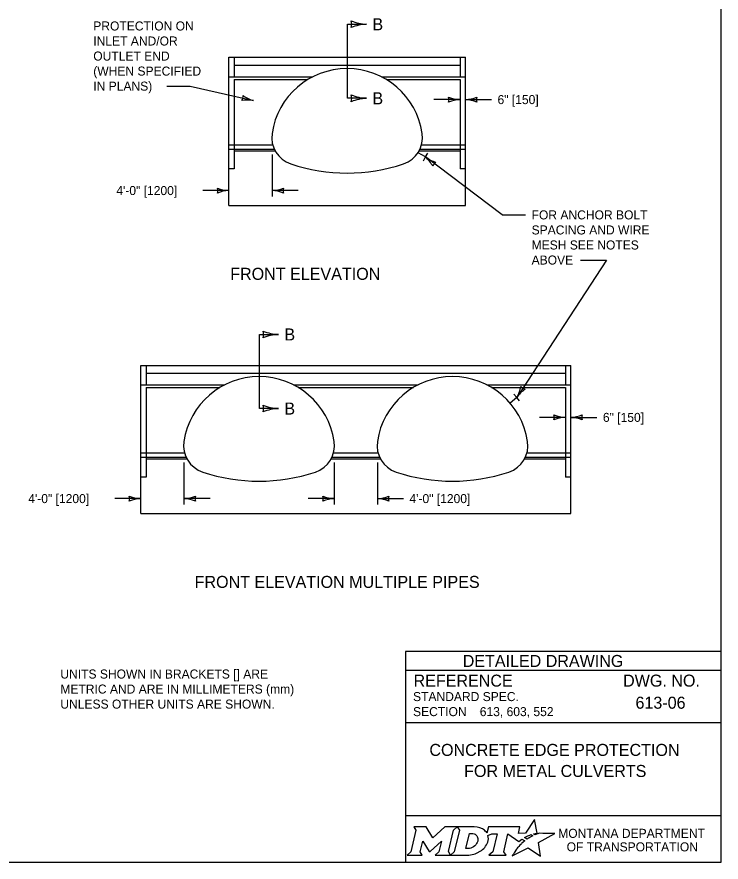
# Model space of a CAD drawing. Extents: x 49991.4 to 50021, y 49987.6 to 50011.4.
# Drawn here: x 50003.93 to 50008.61, y 50000.06 to 50005.68 of the extents above; entities that cross this region are included whole.
import ezdxf

# ---------------------------------------------------------------- set-up
doc = ezdxf.new("R2010")
doc.units = 0
for name, color, linetype in [('Level 1', 7, 'Continuous'), ('Level 2', 7, 'Continuous'), ('Level 3', 7, 'Continuous'), ('Level 4', 7, 'Continuous'), ('Level 6', 7, 'Continuous')]:
    doc.layers.add(name, color=color, linetype=linetype)

msp = doc.modelspace()

# ---------------------------------------------------------------- linework, layer by layer
at = {"layer": 'Level 1'}
for p, q in [((50005.3392, 50004.4278), (50005.3392, 50005.4139)), ((50005.3392, 50005.4139), (50006.9137, 50005.4139)), ((50006.9137, 50004.4278), (50006.9137, 50005.4139)), ((50005.3392, 50004.8321), (50005.6311, 50004.8321)), ((50006.6219, 50004.8324), (50006.9137, 50004.8324)), ((50005.3392, 50004.8032), (50005.6415, 50004.8032)), ((50006.6481, 50004.751), (50006.5984, 50004.7796)), ((50006.6113, 50004.8032), (50006.9137, 50004.8032)), ((50006.6481, 50004.751), (50006.6625, 50004.7759)), ((50006.6336, 50004.726), (50006.6481, 50004.751)), ((50005.3392, 50004.4278), (50006.9137, 50004.4278)), ((50004.7532, 50002.3794), (50004.7532, 50003.3655)), ((50004.7532, 50003.3655), (50007.6147, 50003.3655)), ((50007.6147, 50002.3794), (50007.6147, 50003.3655)), ((50007.2545, 50003.1521), (50007.2101, 50003.1149)), ((50007.2545, 50003.1521), (50007.2359, 50003.1738)), ((50007.2729, 50003.1299), (50007.2545, 50003.1521)), ((50004.7532, 50002.7837), (50005.0451, 50002.7837)), ((50004.7533, 50002.7548), (50005.0556, 50002.7548)), ((50006.0253, 50002.7548), (50006.3426, 50002.7548)), ((50006.0358, 50002.7837), (50006.3321, 50002.7837)), ((50007.3123, 50002.7548), (50007.6147, 50002.7548)), ((50007.3228, 50002.7837), (50007.6147, 50002.7837)), ((50004.7532, 50002.3794), (50007.6147, 50002.3794))]:
    msp.add_line(p, q, dxfattribs=at)
msp.add_lwpolyline([(50008.6146, 50011.2628), (50000.3356, 50011.2628), (50000.3356, 50000.0624), (50008.6146, 50000.0624)], close=True, dxfattribs=at)
for centre, radius, start, end in [((50006.1264, 50004.8333), 0.5053, 8.4935, 171.5065), ((50005.8103, 50004.8805), 0.1857, 171.5065, 251.5631), ((50006.4425, 50004.8805), 0.1857, 288.4369, 8.4935), ((50006.1264, 50005.8288), 1.1852, 251.5631, 288.4369), ((50005.5405, 50002.785), 0.5053, 8.4935, 171.5065), ((50006.8274, 50002.785), 0.5053, 8.4935, 171.5065), ((50005.2243, 50002.8322), 0.1857, 171.5065, 251.5631), ((50005.8566, 50002.8322), 0.1857, 288.4369, 8.4935), ((50006.5113, 50002.8322), 0.1857, 171.5065, 251.5631), ((50007.1436, 50002.8322), 0.1857, 288.4369, 8.4935), ((50005.5405, 50003.7805), 1.1852, 251.5631, 288.4369), ((50006.8274, 50003.7805), 1.1852, 251.5631, 288.4369)]:
    msp.add_arc(centre, radius, start, end, dxfattribs=at)
at = {"layer": 'Level 2'}
for p, q in [((50008.6146, 50001.4624), (50006.5146, 50001.4624)), ((50006.5146, 50001.4624), (50006.5146, 50000.0624)), ((50008.6146, 50001.3374), (50006.5146, 50001.3374)), ((50008.2507, 50001.1223), (50008.2507, 50001.1223)), ((50007.0089, 50001.0629), (50007.0089, 50001.0629)), ((50008.6146, 50000.9874), (50006.5146, 50000.9874)), ((50007.5646, 50000.7383), (50007.5646, 50000.7383)), ((50008.6146, 50000.3693), (50006.5146, 50000.3693))]:
    msp.add_line(p, q, dxfattribs=at)
for points in [[(50007.3771, 50000.2447), (50007.3668, 50000.2503), (50007.3784, 50000.2531), (50007.39, 50000.2551), (50007.3726, 50000.3452), (50007.3131, 50000.2539), (50007.2658, 50000.2532), (50007.2761, 50000.2973), (50007.0669, 50000.2974), (50007.0568, 50000.2549), (50007.051, 50000.2632)], [(50006.5701, 50000.2974), (50006.5842, 50000.274), (50006.5507, 50000.1307), (50006.525, 50000.1082), (50006.6266, 50000.1082), (50006.6131, 50000.131), (50006.6293, 50000.2011), (50006.673, 50000.1321), (50006.6783, 50000.1321), (50006.7534, 50000.2016), (50006.737, 50000.1305), (50006.7123, 50000.1085), (50006.8139, 50000.1085), (50006.8001, 50000.1318), (50006.8333, 50000.2742)], [(50006.8333, 50000.2742), (50006.8586, 50000.2974), (50006.7762, 50000.2974), (50006.6966, 50000.2244), (50006.6521, 50000.2971), (50006.5701, 50000.2974)], [(50006.9722, 50000.2974), (50006.8586, 50000.2974), (50006.8733, 50000.2745), (50006.8394, 50000.1307), (50006.8139, 50000.1085), (50006.9245, 50000.1085)], [(50006.9962, 50000.2107), (50006.995, 50000.2026), (50006.9918, 50000.1933), (50006.9876, 50000.1851), (50006.982, 50000.1776), (50006.9755, 50000.1707), (50006.9676, 50000.1644), (50006.9593, 50000.1597), (50006.9502, 50000.1558), (50006.9411, 50000.1535), (50006.9319, 50000.1526), (50006.916, 50000.1526), (50006.9396, 50000.2526), (50006.9556, 50000.2526), (50006.9632, 50000.252), (50006.9708, 50000.2501), (50006.9774, 50000.2471), (50006.9835, 50000.2429), (50006.9883, 50000.2379), (50006.992, 50000.2319), (50006.9947, 50000.2257), (50006.9963, 50000.2183), (50006.9963, 50000.2153), (50006.9962, 50000.2107)], [(50007.0636, 50000.2383), (50007.0882, 50000.2514), (50007.1251, 50000.2514), (50007.0965, 50000.1309), (50007.069, 50000.1082), (50007.1852, 50000.1082), (50007.1682, 50000.1311), (50007.1964, 50000.2513), (50007.2677, 50000.1996), (50007.2888, 50000.2147), (50007.3085, 50000.2038)], [(50007.2527, 50000.1479), (50007.2374, 50000.1235), (50007.2327, 50000.116), (50007.2269, 50000.1074), (50007.2246, 50000.1031), (50007.3299, 50000.1562), (50007.4138, 50000.1011), (50007.4007, 50000.1938), (50007.5076, 50000.2522), (50007.4583, 50000.253), (50007.4282, 50000.2534), (50007.4074, 50000.2537), (50007.4006, 50000.2522), (50007.3957, 50000.251), (50007.3873, 50000.2487), (50007.3771, 50000.2447)], [(50007.3267, 50000.2171), (50007.3243, 50000.2154), (50007.306, 50000.225), (50007.3163, 50000.2307), (50007.3204, 50000.2329), (50007.329, 50000.2369), (50007.3347, 50000.2395), (50007.3426, 50000.2425), (50007.3499, 50000.2452), (50007.3617, 50000.2378), (50007.3577, 50000.2357), (50007.3531, 50000.2332), (50007.3489, 50000.231), (50007.3439, 50000.2281), (50007.342, 50000.227), (50007.3393, 50000.2254), (50007.3368, 50000.224), (50007.3345, 50000.2224), (50007.3319, 50000.2206), (50007.3292, 50000.2188), (50007.3267, 50000.2171)], [(50007.2666, 50000.164), (50007.2666, 50000.164)], [(50006.9702, 50000.1158), (50006.9786, 50000.1184), (50006.9916, 50000.1238), (50007.012, 50000.1348)]]:
    msp.add_lwpolyline(points, dxfattribs=at)
for centre, radius, start, end in [((50006.9953, 50000.219), 0.0709, 339.5329, 15.8582), ((50006.9513, 50000.2363), 0.1183, 300.9103, 339.1383)]:
    msp.add_arc(centre, radius, start, end, dxfattribs=at)
for centre, major_axis, ratio, start_param, end_param in [((50006.9701, 50000.25), (0.0834, -0.0037), 0.568097, 0.61298, 1.570796), ((50007.0257, 50000.2573), (0.0361, -0.0295), 0.469099, 1.225588, 1.570796), ((50007.2597, 50000.1559), (-0.00694, -0.00806), 0.008222, 0, 3.137361), ((50007.2764, 50000.1742), (-0.0098, -0.0102), 0.016458, 3.141593, 6.279097), ((50007.2974, 50000.1941), (-0.0112, -0.0097), 0.021651, 3.157348, 6.283185), ((50006.9248, 50000.2568), (0, 0.1484), 0.987302, 3.139398, 3.456847)]:
    msp.add_ellipse(centre, major_axis=major_axis, ratio=ratio, start_param=start_param, end_param=end_param, dxfattribs=at)
at = {"layer": 'Level 3'}
for p, q in [((50004.9262, 50005.2221), (50005.0829, 50005.2221)), ((50005.0829, 50005.2221), (50005.5041, 50005.1256)), ((50006.8777, 50005.1324), (50006.7043, 50005.1324)), ((50006.9137, 50005.1326), (50007.0871, 50005.1326)), ((50005.6267, 50004.7679), (50005.6267, 50004.4878)), ((50007.1571, 50004.3658), (50006.6481, 50004.751)), ((50005.3392, 50004.5278), (50005.1658, 50004.5278)), ((50005.8001, 50004.5278), (50005.6267, 50004.5278)), ((50007.1571, 50004.3658), (50007.3138, 50004.3658)), ((50007.8511, 50004.0658), (50007.2545, 50003.1521)), ((50007.6786, 50004.0658), (50007.8511, 50004.0658)), ((50007.5787, 50003.0194), (50007.4053, 50003.0194)), ((50007.6147, 50003.0194), (50007.7881, 50003.0194)), ((50005.0407, 50002.7196), (50005.0407, 50002.4394)), ((50006.0402, 50002.7196), (50006.0402, 50002.4394)), ((50006.3277, 50002.7196), (50006.3277, 50002.4394)), ((50004.7532, 50002.4794), (50004.5798, 50002.4794)), ((50005.2141, 50002.4794), (50005.0407, 50002.4794)), ((50006.0402, 50002.4794), (50005.8668, 50002.4794)), ((50006.3277, 50002.4794), (50006.5011, 50002.4794))]:
    msp.add_line(p, q, dxfattribs=at)
for centre, radius, start, end in [((50006.2671, 50005.9297), 0.2964, 247.456, 267.6395), ((50006.0839, 50005.6335), 0.073, 342.1388, 17.8612), ((50006.2702, 50005.3232), 0.3107, 92.8273, 112.0772), ((50005.3791, 50005.1543), 0.0548, 329.2405, 4.9629), ((50005.5626, 50005.3401), 0.2223, 234.5577, 254.7412), ((50006.2671, 50005.4372), 0.2964, 247.456, 267.6395), ((50006.0839, 50005.141), 0.073, 342.1388, 17.8612), ((50005.4634, 50004.8962), 0.233, 79.929, 99.1789), ((50006.2702, 50004.8307), 0.3107, 92.8273, 112.0772), ((50006.8868, 50005.3545), 0.2223, 247.456, 267.6395), ((50006.7495, 50005.1324), 0.0548, 342.1388, 17.8612), ((50006.8892, 50004.8997), 0.233, 92.8273, 112.0772), ((50006.9022, 50005.3653), 0.233, 272.8273, 292.0772), ((50006.9045, 50004.9105), 0.2223, 67.456, 87.6395), ((50007.0419, 50005.1326), 0.0548, 162.1388, 197.8612), ((50006.4997, 50004.5853), 0.2223, 27.9694, 48.1529), ((50006.7872, 50004.9379), 0.233, 233.3407, 252.5906), ((50006.747, 50004.6694), 0.0548, 122.6522, 158.3746), ((50005.3483, 50004.7499), 0.2223, 247.456, 267.6395), ((50005.211, 50004.5278), 0.0548, 342.1388, 17.8612), ((50005.6152, 50004.7605), 0.233, 272.8273, 292.0772), ((50005.7549, 50004.5278), 0.0548, 162.1388, 197.8612), ((50005.3507, 50004.2951), 0.233, 92.8273, 112.0772), ((50005.6175, 50004.3057), 0.2223, 67.456, 87.6395), ((50005.6812, 50003.867), 0.2964, 247.456, 267.6395), ((50005.498, 50003.5708), 0.073, 342.1388, 17.8612), ((50005.6843, 50003.2605), 0.3107, 92.8273, 112.0772), ((50007.0534, 50003.2697), 0.233, 329.6853, 348.9351), ((50007.4355, 50003.023), 0.2223, 124.314, 144.4975), ((50007.3246, 50003.2595), 0.0548, 218.9968, 254.7191), ((50005.6812, 50003.3745), 0.2964, 247.456, 267.6395), ((50005.498, 50003.0783), 0.073, 342.1388, 17.8612), ((50005.6843, 50002.768), 0.3107, 92.8273, 112.0772), ((50007.5879, 50003.2415), 0.2223, 247.456, 267.6395), ((50007.4505, 50003.0194), 0.0548, 342.1388, 17.8612), ((50007.6032, 50003.2521), 0.233, 272.8273, 292.0772), ((50007.7429, 50003.0194), 0.0548, 162.1388, 197.8612), ((50007.5902, 50002.7867), 0.233, 92.8273, 112.0772), ((50007.6055, 50002.7973), 0.2223, 67.456, 87.6395), ((50004.7624, 50002.7015), 0.2223, 247.456, 267.6395), ((50004.625, 50002.4794), 0.0548, 342.1388, 17.8612), ((50004.7647, 50002.2467), 0.233, 92.8273, 112.0772), ((50005.0292, 50002.7121), 0.233, 272.8273, 292.0772), ((50005.0315, 50002.2573), 0.2223, 67.456, 87.6395), ((50005.1689, 50002.4794), 0.0548, 162.1388, 197.8612), ((50006.0494, 50002.7015), 0.2223, 247.456, 267.6395), ((50005.912, 50002.4794), 0.0548, 342.1388, 17.8612), ((50006.0517, 50002.2467), 0.233, 92.8273, 112.0772), ((50006.3162, 50002.7121), 0.233, 272.8273, 292.0772), ((50006.3185, 50002.2573), 0.2223, 67.456, 87.6395), ((50006.4559, 50002.4794), 0.0548, 162.1388, 197.8612)]:
    msp.add_arc(centre, radius, start, end, dxfattribs=at)
at = {"layer": 'Level 4'}
for p, q in [((50005.3751, 50005.4139), (50005.3751, 50005.284)), ((50006.8777, 50005.4139), (50006.8777, 50005.2846)), ((50005.3751, 50005.3625), (50006.8777, 50005.3625)), ((50005.3392, 50005.284), (50005.8985, 50005.284)), ((50006.3547, 50005.2846), (50006.9137, 50005.2846)), ((50005.3751, 50005.2667), (50005.3751, 50004.6714)), ((50005.3751, 50005.2667), (50005.8624, 50005.2667)), ((50006.3875, 50005.2668), (50006.8777, 50005.2668)), ((50006.8777, 50005.2668), (50006.8777, 50004.6712)), ((50005.3751, 50004.7916), (50005.6473, 50004.7916)), ((50006.6053, 50004.7912), (50006.8777, 50004.7912)), ((50005.3751, 50004.6714), (50005.3392, 50004.6714)), ((50006.9137, 50004.6712), (50006.8777, 50004.6712)), ((50004.7891, 50003.3655), (50004.7891, 50003.2356)), ((50007.5787, 50003.3655), (50007.5787, 50003.2356)), ((50004.7891, 50003.3141), (50007.5787, 50003.3141)), ((50004.7532, 50003.2356), (50005.3118, 50003.2356)), ((50004.7891, 50003.2183), (50004.7891, 50002.623)), ((50004.7891, 50003.2183), (50005.2805, 50003.2183)), ((50005.7691, 50003.2356), (50006.5988, 50003.2356)), ((50005.8004, 50003.2183), (50006.5675, 50003.2183)), ((50007.0561, 50003.2356), (50007.6147, 50003.2356)), ((50007.0874, 50003.2183), (50007.5787, 50003.2183)), ((50007.5787, 50003.2183), (50007.5787, 50002.6228)), ((50004.7891, 50002.7432), (50005.0614, 50002.7432)), ((50006.0195, 50002.7432), (50006.3484, 50002.7432)), ((50007.3065, 50002.7432), (50007.5787, 50002.7432)), ((50004.7891, 50002.623), (50004.7529, 50002.623)), ((50007.6148, 50002.6228), (50007.5787, 50002.6228))]:
    msp.add_line(p, q, dxfattribs=at)
at = {"layer": 'Level 6'}
for p, q in [((50006.1285, 50005.6335), (50006.2549, 50005.6335)), ((50006.1285, 50005.335), (50006.1285, 50005.6335)), ((50006.1285, 50005.141), (50006.1285, 50005.335)), ((50006.2549, 50005.141), (50006.1285, 50005.141)), ((50005.5426, 50003.5708), (50005.669, 50003.5708)), ((50005.5426, 50003.2723), (50005.5426, 50003.5708)), ((50005.5426, 50003.0783), (50005.5426, 50003.2723)), ((50005.669, 50003.0783), (50005.5426, 50003.0783))]:
    msp.add_line(p, q, dxfattribs=at)

# ---------------------------------------------------------------- texts
at = {"layer": 'Level 2'}
for s, height, p in [('B', 0.08, (50006.2949, 50005.5935)), ('PROTECTION ON', 0.06, (50004.4374, 50005.5921)), ('INLET AND/OR', 0.06, (50004.4374, 50005.4921)), ('OUTLET END', 0.06, (50004.4374, 50005.3921)), ('(WHEN SPECIFIED', 0.06, (50004.4374, 50005.2921)), ('IN PLANS)', 0.06, (50004.4374, 50005.1921)), ('B', 0.08, (50006.2949, 50005.101)), ('6" [150]', 0.06, (50007.1271, 50005.1026)), ('4\'-0" [1200]', 0.06, (50004.5907, 50004.4978)), ('FOR ANCHOR BOLT', 0.06, (50007.3538, 50004.3358)), ('SPACING AND WIRE', 0.06, (50007.3538, 50004.2358)), ('MESH SEE NOTES', 0.06, (50007.3538, 50004.1358)), ('ABOVE', 0.06, (50007.3538, 50004.0358)), ('FRONT ELEVATION', 0.08, (50005.3486, 50003.9339)), ('B', 0.08, (50005.709, 50003.5308)), ('B', 0.08, (50005.709, 50003.0383)), ('6" [150]', 0.06, (50007.8281, 50002.9894)), ('4\'-0" [1200]', 0.06, (50004.0047, 50002.4494)), ('4\'-0" [1200]', 0.06, (50006.5411, 50002.4494)), ('FRONT ELEVATION MULTIPLE PIPES', 0.08, (50005.1117, 50001.8855)), ('DETAILED DRAWING', 0.0799, (50006.8956, 50001.3599)), ('UNITS SHOWN IN BRACKETS [] ARE ', 0.06, (50004.2183, 50001.283)), ('REFERENCE', 0.08, (50006.5682, 50001.229)), ('DWG. NO.', 0.08, (50007.9624, 50001.229)), ('METRIC AND ARE IN MILLIMETERS (mm) ', 0.06, (50004.2183, 50001.183)), ('STANDARD SPEC.', 0.06, (50006.5649, 50001.133)), ('UNLESS OTHER UNITS ARE SHOWN.', 0.06, (50004.2183, 50001.083)), ('613-06', 0.08, (50008.0449, 50001.0823)), ('SECTION', 0.06, (50006.5649, 50001.033)), ('613, 603, 552', 0.06, (50007.0089, 50001.0329)), ('CONCRETE EDGE PROTECTION', 0.08, (50006.6738, 50000.7683)), ('FOR METAL CULVERTS', 0.08, (50006.9049, 50000.6283)), ('MONTANA DEPARTMENT', 0.06, (50007.5308, 50000.2236)), ('OF TRANSPORTATION', 0.06, (50007.587, 50000.1336))]:
    msp.add_text(s, height=height, dxfattribs=at).set_placement(p)

doc.saveas('drawing.dxf')
